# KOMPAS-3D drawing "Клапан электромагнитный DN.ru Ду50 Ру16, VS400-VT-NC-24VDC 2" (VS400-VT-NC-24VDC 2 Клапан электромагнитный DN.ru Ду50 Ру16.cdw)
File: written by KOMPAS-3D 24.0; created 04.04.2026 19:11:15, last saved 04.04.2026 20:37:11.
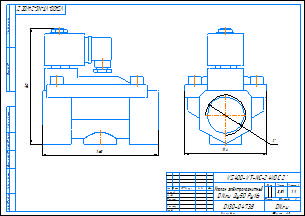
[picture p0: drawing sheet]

Document properties: c3d_UniqueCompID: ef56311e-7521-43dc-8291-0e6108b3d81d; Обозначение: VS400-ET-NC-220VAC 2; Наименование: Клапан электромагнитный DN.ru Ду50 Ру16; Автор: artio; Класс точности: c; Знак неуказанной шероховатости: Шероховатость не задана; Рассекать на разрезах: Да; c3d_UniqueCompID: ef56311e-7521-43dc-8291-0e6108b3d81d; Обозначение: VS400-ET-NC-220VAC 1; Наименование: Клапан электромагнитный DN.ru Ду25 Ру16; Автор: artio; Класс точности: c; Знак неуказанной шероховатости: Шероховатость не задана; Рассекать на разрезах: Да; c3d_UniqueCompID: ef56311e-7521-43dc-8291-0e6108b3d81d; Обозначение: VS400-ET-NC-220VAC 1-2; Наименование: Клапан электромагнитный DN.ru Ду15 Ру16; Автор: artio; Класс точности: c; Знак неуказанной шероховатости: Шероховатость не задана; Рассекать на разрезах: Да; c3d_UniqueCompID: ef56311e-7521-43dc-8291-0e6108b3d81d; Обозначение: VS400-ET-NC-220VAC 3-4; Наименование: Клапан электромагнитный DN.ru Ду20 Ру16; Автор: artio; Класс точности: c; Знак неуказанной шероховатости: Шероховатость не задана; Рассекать на разрезах: Да; c3d_UniqueCompID: ef56311e-7521-43dc-8291-0e6108b3d81d; Обозначение: VS400-ET-NC-220VAC 1 1-4; Наименование: Клапан электромагнитный DN.ru Ду32 Ру16; Автор: artio; Класс точности: c; Знак неуказанной шероховатости: Шероховатость не задана; Рассекать на разрезах: Да; c3d_UniqueCompID: ef56311e-7521-43dc-8291-0e6108b3d81d; Обозначение: VS400-ET-NC-220VAC 3-8; Наименование: Клапан электромагнитный DN.ru Ду10 Ру16; Автор: artio; Класс точности: c; Знак неуказанной шероховатости: Шероховатость не задана; Рассекать на разрезах: Да; c3d_UniqueCompID: ef56311e-7521-43dc-8291-0e6108b3d81d; Обозначение: VS400-ET-NC-220VAC 1 1-2; Наименование: Клапан электромагнитный DN.ru Ду40 Ру16; Автор: artio; Класс точности: c; Знак неуказанной шероховатости: Шероховатость не задана; Рассекать на разрезах: Да; Автор: artio; Форматы листов документа: A3; Полное имя файла: VS400-VT-NC-24VDC 2 Клапан электромагнитный DN.ru Ду50 Ру16.m3d; Масса: 3.509; Наименование: Клапан электромагнитный DN.ru Ду50 Ру16; Количество листов документа: 1; Примечание: D130-04738

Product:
- Body: Тело 1  | qty 1
    Масса: 7.119215
- Part/product: Клапан электромагнитный DN.ru Ду50 Ру16  | designation VS400-VT-NC-24VDC 2
    Масса: 3.509
    Раздел спецификации: Прочие изделия
    Примечание: D130-04738
    additional columns: ef56311e-7521-43dc-8291-0e6108b3d81d; VS400-ET-NC-220VAC 2; artio; c; Шероховатость не задана; Да

Views: Вид 1, Спереди
Referenced files in C:\Users\artio\OneDrive\Рабочий стол\Клапан электромагнитный DN.ru\VS400-ET-NC\VS400-ET-NC-24VDC\: VS400-ET-NC-24VDC 3-8 Клапан электромагнитный DN.ru Ду10 Ру16.m3d
Referenced files in C:\Users\artio\OneDrive\Рабочий стол\Клапан электромагнитный DN.ru\VS400-VT-NC\VS400-VT-NC-24VDC\: VS400-VT-NC-24VDC 2 Клапан электромагнитный DN.ru Ду50 Ру16.m3d
Referenced files in C:\Users\artio\OneDrive\Рабочий стол\Клапан электромагнитный DN.ru\VS400-ET-NC\: VS400-ET-NC-24VDC 3-8 Клапан электромагнитный DN.ru Ду10 Ру16.cdw
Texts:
  VS400-VT-NC-24VDC 2
  Клапан электромагнитный
  DN.ru Ду50 Ру16
  VS400-VT-NC-24VDC 2"
  VS400-VT-NC-24VDC 2"-
  Клапан электромагнитный DN.ru Ду50 Ру16
  VS400-VT-NC-24VDC 2 Клапан электромагнитный DN.ru Ду50 Ру16
Dimensions and other numbers on the sheet: 0; 3; 2; 4; 114; 1:1; 1; 3,51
